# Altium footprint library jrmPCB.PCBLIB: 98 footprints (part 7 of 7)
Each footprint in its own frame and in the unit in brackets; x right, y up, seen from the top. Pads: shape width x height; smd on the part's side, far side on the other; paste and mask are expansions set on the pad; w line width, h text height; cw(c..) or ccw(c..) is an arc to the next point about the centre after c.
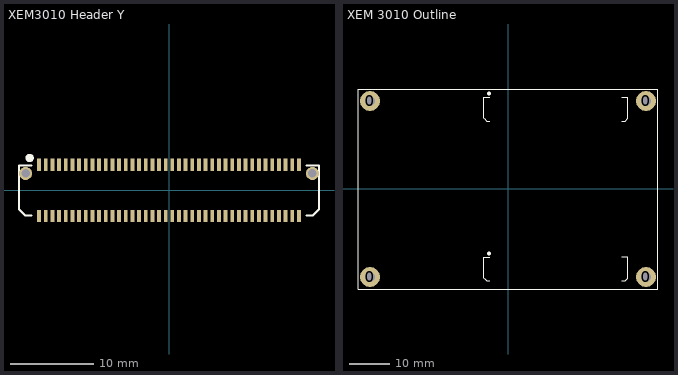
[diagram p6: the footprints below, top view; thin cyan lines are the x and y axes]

## XEM3010 Header Y [mm]
pads (82):
  rect 0.46x1.45 smd: Y1(-15.6,3.085) Y2(-15.6,-3.085) Y3(-14.8,3.085) Y4(-14.8,-3.085) Y5(-14,3.085) Y6(-14,-3.085) Y7(-13.2,3.085) Y8(-13.2,-3.085) Y9(-12.4,3.085) Y10(-12.4,-3.085) Y11(-11.6,3.085) Y12(-11.6,-3.085) Y13(-10.8,3.085) Y14(-10.8,-3.085) Y15(-10,3.085) Y16(-10,-3.085) Y17(-9.2,3.085) Y18(-9.2,-3.085) Y19(-8.4,3.085) Y20(-8.4,-3.085) Y21(-7.6,3.085) Y22(-7.6,-3.085) Y23(-6.8,3.085) Y24(-6.8,-3.085) Y25(-6,3.085) Y26(-6,-3.085) Y27(-5.2,3.085) Y28(-5.2,-3.085) Y29(-4.4,3.085) Y30(-4.4,-3.085) Y31(-3.6,3.085) Y32(-3.6,-3.085) Y33(-2.8,3.085) Y34(-2.8,-3.085) Y35(-2,3.085) Y36(-2,-3.085) Y37(-1.2,3.085) Y38(-1.2,-3.085) Y39(-0.4,3.085) Y40(-0.4,-3.085) Y41(0.4,3.085) Y42(0.4,-3.085) Y43(1.2,3.085) Y44(1.2,-3.085) Y45(2,3.085) Y46(2,-3.085) Y47(2.8,3.085) Y48(2.8,-3.085) Y49(3.6,3.085) Y50(3.6,-3.085) Y51(4.4,3.085) Y52(4.4,-3.085) Y53(5.2,3.085) Y54(5.2,-3.085) Y55(6,3.085) Y56(6,-3.085) Y57(6.8,3.085) Y58(6.8,-3.085) Y59(7.6,3.085) Y60(7.6,-3.085) Y61(8.4,3.085) Y62(8.4,-3.085) Y63(9.2,3.085) Y64(9.2,-3.085) Y65(10,3.085) Y66(10,-3.085) Y67(10.8,3.085) Y68(10.8,-3.085) Y69(11.6,3.085) Y70(11.6,-3.085) Y71(12.4,3.085) Y72(12.4,-3.085) Y73(13.2,3.085) Y74(13.2,-3.085) Y75(14,3.085) Y76(14,-3.085) Y77(14.8,3.085) Y78(14.8,-3.085) Y79(15.6,3.085) Y80(15.6,-3.085)
  round 1.575 hole 1.016: Y81(-17.235,2.035) Y82(17.235,2.035)
Top Overlay:
  circle w0.5: c-16.75,3.9 r0.25
  lines w0.254: -16.5,-3 -17.3,-3 -18,-2.3 -18,3 -16.5,3 ; 16.5,-3 17.3,-3 18,-2.3 18,3 16.5,3

## XEM 3010 Outline [mm]
pads (4):
  round 5 hole 2.5: 0(-34.5,-22.017) 0(-34.5,21.983) 0(34.5,-22.017) 0(34.5,21.983)
Top Overlay:
  circle w0.5: c-4.75,23.882 r0.25
  circle w0.5: c-4.75,-16.118 r0.25
  lines w0.203: -37.5,-25.018 -37.5,24.982 37.5,24.982 37.5,-25.018 -37.5,-25.018
  lines w0.254: -4.5,-23.018 -5.3,-23.018 -6,-22.318 -6,-17.018 -4.5,-17.018 ; -4.5,16.982 -5.3,16.982 -6,17.682 -6,22.982 -4.5,22.982 ; 28.5,-23.018 29.3,-23.018 30,-22.318 30,-17.018 28.5,-17.018 ; 28.5,16.982 29.3,16.982 30,17.682 30,22.982 28.5,22.982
